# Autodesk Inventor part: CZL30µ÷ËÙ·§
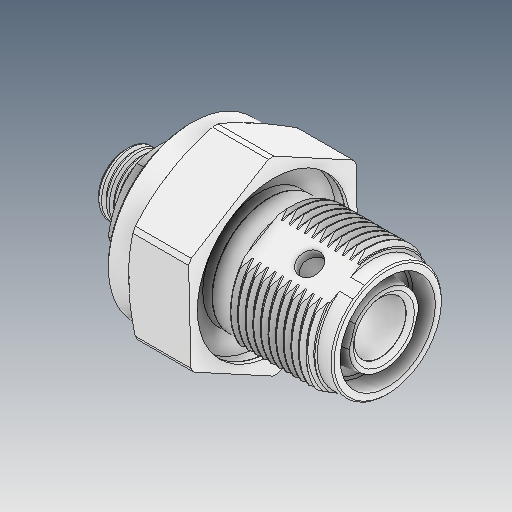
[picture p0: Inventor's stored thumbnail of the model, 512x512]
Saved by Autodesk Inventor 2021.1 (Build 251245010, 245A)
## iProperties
Created: 2021-05
Part Number: CZL30µ÷ËÙ·§
Material: Ogólny
Document SubType Name: Modeling
Designer: user
Density: 1 g/cm^3
Appearance: Domyślna
Author: user
Revision Number: ÈÎºÎ
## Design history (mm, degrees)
feature "ÊäÈë1"
feature "ÊäÈë4"
feature "ÊäÈë5"
node "Bryła1"
node "Bryła2"
node "Bryła3"
